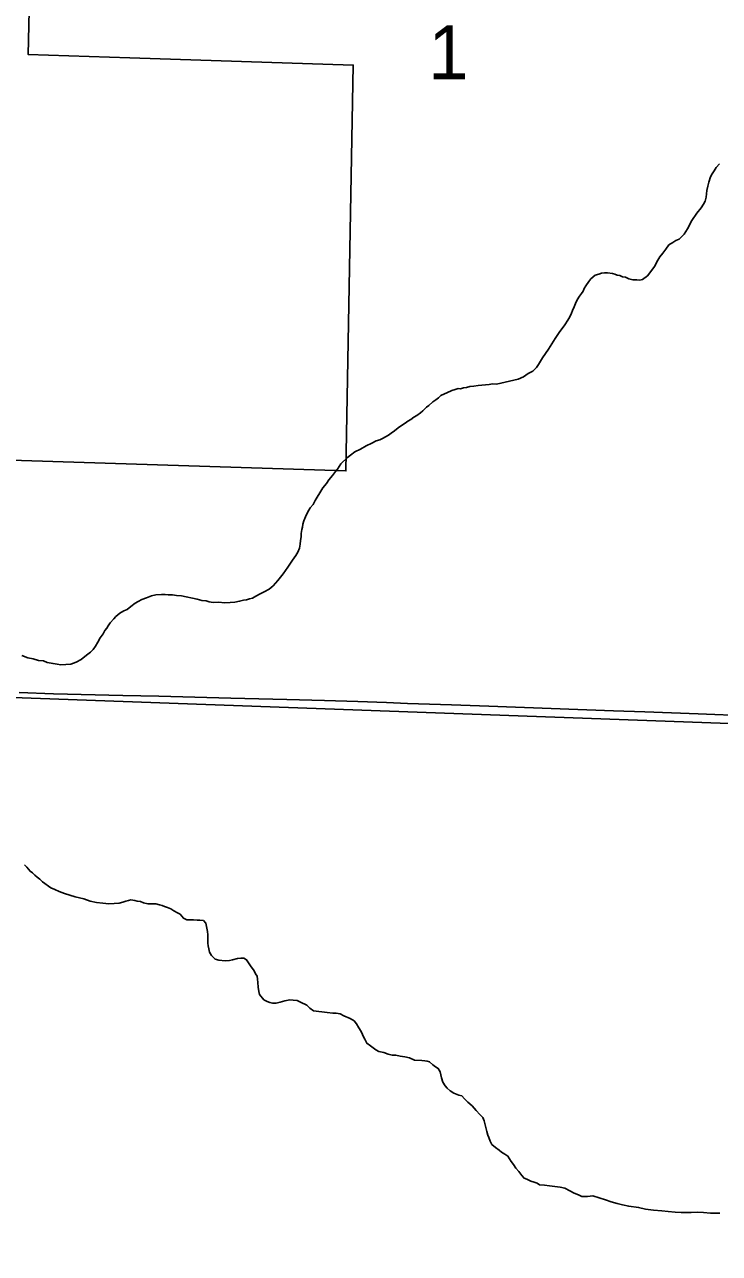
# Model space of a CAD drawing. Extents: x 0 to 34, y 0 to 22.
# Drawn here: x 6.622 to 7.163, y 14.904 to 15.859 of the extents above; entities that cross this region are included whole.
import ezdxf

# ---------------------------------------------------------------- set-up
doc = ezdxf.new("R2010")
doc.units = 0
for name, color, linetype in [('Default', 7, 'Continuous'), ('GM_X_County_Road', 7, 'Continuous'), ('GM_X_Minor_River', 7, 'Continuous'), ('GM_X_Section', 7, 'Continuous'), ('GM_X_Section_Text', 7, 'Continuous')]:
    doc.layers.add(name, color=color, linetype=linetype)

msp = doc.modelspace()

# ---------------------------------------------------------------- linework, layer by layer
at = {"layer": 'Default'}
msp.add_lwpolyline([(6.38702, 16.38807), (6.37183, 15.73038), (6.45349, 15.7281), (6.45237, 15.64429), (6.36989, 15.64692), (6.36733, 15.53569), (6.52294, 15.53156), (6.52172, 15.40421), (6.53761, 15.40378), (6.53837, 15.52309), (6.87235, 15.51249), (6.87794, 15.82798), (6.70429, 15.83364), (6.62511, 15.83621), (6.63591, 16.30343)], dxfattribs=at)
at = {"layer": 'GM_X_County_Road'}
msp.add_lwpolyline([(6.61813, 15.34005), (6.64484, 15.33924), (6.69891, 15.33794), (6.72688, 15.33731), (6.7828, 15.33586), (6.82631, 15.3347), (6.85552, 15.33398), (6.8816, 15.33321), (6.90396, 15.3323), (6.92021, 15.33172), (6.95428, 15.3305), (6.98348, 15.32953), (7.08039, 15.32594), (7.10461, 15.32503), (7.14624, 15.32359), (7.18537, 15.32196)], dxfattribs=at)
at = {"layer": 'GM_X_Minor_River'}
for points in [[(7.02362, 15.59783), (7.0252, 15.60046), (7.02755, 15.60384), (7.02991, 15.60721), (7.03228, 15.61134), (7.03503, 15.61547), (7.03818, 15.61997), (7.0425, 15.62597), (7.04486, 15.62972), (7.04644, 15.63235), (7.04764, 15.63499), (7.04845, 15.63726), (7.04965, 15.63989), (7.05085, 15.64253), (7.05205, 15.64555), (7.05401, 15.64817), (7.05558, 15.65042), (7.05677, 15.6523), (7.05757, 15.65419), (7.05876, 15.65644), (7.06112, 15.65982), (7.06268, 15.66169), (7.06617, 15.66466), (7.06885, 15.66536), (7.07115, 15.66607), (7.07344, 15.6664), (7.07573, 15.66634), (7.07952, 15.66588), (7.08142, 15.66546), (7.08331, 15.66466), (7.0852, 15.66423), (7.08747, 15.66342), (7.08974, 15.66299), (7.09238, 15.66179), (7.09541, 15.66096), (7.09846, 15.66089), (7.10074, 15.66084), (7.10303, 15.66117), (7.1069, 15.66413), (7.11239, 15.67162), (7.11399, 15.67502), (7.11635, 15.67877), (7.11871, 15.68176), (7.12105, 15.68476), (7.12341, 15.68813), (7.1265, 15.68996), (7.12881, 15.69144), (7.1315, 15.69252), (7.1354, 15.69662), (7.13777, 15.70076), (7.14133, 15.70715), (7.14526, 15.71277), (7.14839, 15.71689), (7.15036, 15.71989), (7.15156, 15.72215), (7.15238, 15.72518), (7.15288, 15.7305), (7.15371, 15.7339), (7.15453, 15.73693), (7.15577, 15.74109), (7.15696, 15.74335), (7.15853, 15.7456), (7.16011, 15.74823), (7.16284, 15.75121)], [(6.7444, 15.4152), (6.75653, 15.41264), (6.76032, 15.4118), (6.76373, 15.41134), (6.766, 15.41053), (6.76904, 15.41008), (6.77323, 15.41037), (6.77818, 15.40988), (6.78237, 15.41017), (6.7858, 15.41047), (6.78963, 15.41115), (6.79269, 15.41184), (6.79498, 15.41217), (6.79728, 15.41288), (6.79958, 15.41359), (6.80228, 15.41506), (6.80574, 15.41688), (6.80882, 15.41834), (6.81267, 15.42054), (6.81578, 15.42313), (6.81929, 15.42724), (6.82359, 15.43248), (6.82713, 15.43773), (6.83067, 15.44298), (6.83342, 15.44673), (6.835, 15.44935), (6.8362, 15.45237), (6.83665, 15.45541), (6.83709, 15.45845), (6.83753, 15.4611), (6.83759, 15.46376), (6.83803, 15.4668), (6.83845, 15.46869), (6.83888, 15.47097), (6.8397, 15.47361), (6.84091, 15.47663), (6.8425, 15.48002), (6.84449, 15.48379), (6.84683, 15.4864), (6.84842, 15.48941), (6.85, 15.49204), (6.85197, 15.49542), (6.85434, 15.49918), (6.85707, 15.50255), (6.85904, 15.50555), (6.86178, 15.50891), (6.86413, 15.51191), (6.86569, 15.51377), (6.86845, 15.5179), (6.8735, 15.52274), (6.87582, 15.52459), (6.87931, 15.52718), (6.88354, 15.52937), (6.88817, 15.53193), (6.8924, 15.53412), (6.89587, 15.53595), (6.89855, 15.53665), (6.90086, 15.53774), (6.90317, 15.53883), (6.90548, 15.5403), (6.90742, 15.54178), (6.91012, 15.54363), (6.91283, 15.54585), (6.91554, 15.54769), (6.91825, 15.54954), (6.92056, 15.55101), (6.92288, 15.55248), (6.9252, 15.55433), (6.92751, 15.55542), (6.93022, 15.55765), (6.93216, 15.55913), (6.93489, 15.56211), (6.93682, 15.56321), (6.93993, 15.56619), (6.94224, 15.56766), (6.94418, 15.56914), (6.94612, 15.571), (6.94882, 15.57246), (6.95074, 15.57318), (6.95458, 15.575), (6.95726, 15.5757), (6.95956, 15.57641), (6.96147, 15.57637), (6.96377, 15.57708), (6.96606, 15.57741), (6.96874, 15.57811), (6.97179, 15.57842), (6.97523, 15.57873), (6.9779, 15.57905), (6.98095, 15.57936), (6.98363, 15.57969), (6.9863, 15.58001), (6.98934, 15.57994), (6.99278, 15.58062), (7.00618, 15.58375), (7.01041, 15.58556), (7.01389, 15.58815), (7.01774, 15.58997), (7.02046, 15.59295), (7.02204, 15.5952), (7.02362, 15.59783)], [(6.62041, 15.36884), (6.62494, 15.36721), (6.62911, 15.36636), (6.63328, 15.36513), (6.63707, 15.36466), (6.6401, 15.36345), (6.64464, 15.36259), (6.64768, 15.36214), (6.65072, 15.36169), (6.65453, 15.36199), (6.65835, 15.36228), (6.66257, 15.36371), (6.66642, 15.36591), (6.67068, 15.36924), (6.67378, 15.37146), (6.67573, 15.3737), (6.67769, 15.37632), (6.67928, 15.37933), (6.68125, 15.38272), (6.6836, 15.38571), (6.6848, 15.38835), (6.68636, 15.39021), (6.68754, 15.39209), (6.68911, 15.39434), (6.69185, 15.39733), (6.69341, 15.3992), (6.69651, 15.40179), (6.6996, 15.40363), (6.70228, 15.40471), (6.705, 15.40693), (6.70848, 15.40952), (6.7108, 15.41099), (6.71349, 15.41246), (6.71733, 15.41389), (6.72117, 15.41533), (6.72461, 15.41602), (6.72881, 15.4163), (6.73185, 15.41624), (6.73414, 15.41619), (6.73756, 15.41611), (6.7406, 15.41566), (6.7444, 15.4152)], [(6.62227, 15.20623), (6.62413, 15.20429), (6.62673, 15.20119), (6.62861, 15.2), (6.63047, 15.19806), (6.63234, 15.19649), (6.63421, 15.19493), (6.63646, 15.19298), (6.64283, 15.18827), (6.64585, 15.18706), (6.64924, 15.18546), (6.6534, 15.18384), (6.65756, 15.18261), (6.66172, 15.18138), (6.66854, 15.1797), (6.67346, 15.17807), (6.67838, 15.17682), (6.68332, 15.17633), (6.68788, 15.17585), (6.69207, 15.17613), (6.69589, 15.17643)], [(6.69589, 15.17643), (6.69895, 15.17712), (6.70125, 15.17783), (6.70317, 15.17855), (6.70508, 15.17889), (6.70812, 15.17844), (6.71001, 15.17802), (6.71267, 15.17758), (6.71494, 15.17677), (6.71835, 15.17593), (6.72025, 15.17589), (6.72215, 15.17585), (6.72443, 15.1758), (6.72746, 15.17497), (6.72936, 15.17454), (6.73125, 15.17374), (6.73351, 15.17293), (6.73616, 15.17211), (6.73841, 15.17054), (6.74143, 15.16895), (6.7433, 15.16776), (6.7459, 15.16466), (6.74854, 15.16346), (6.75387, 15.16334), (6.75653, 15.16328), (6.75882, 15.16323), (6.76148, 15.16279), (6.76334, 15.16085), (6.76472, 15.15434), (6.76505, 15.15167), (6.765, 15.14939), (6.76496, 15.14749), (6.76491, 15.1452), (6.76525, 15.14329), (6.76558, 15.141), (6.76628, 15.13832), (6.76775, 15.13562), (6.77074, 15.13289), (6.77339, 15.13207), (6.77832, 15.13158), (6.78176, 15.13189), (6.78405, 15.13222), (6.78788, 15.13327), (6.79056, 15.13359), (6.79284, 15.13354), (6.7951, 15.13235), (6.79804, 15.12772), (6.80101, 15.12384), (6.8021, 15.12154), (6.8032, 15.11961), (6.80353, 15.11732), (6.80386, 15.11464), (6.80417, 15.11121), (6.80447, 15.10778), (6.80519, 15.10548), (6.80852, 15.10122), (6.81116, 15.10002), (6.81305, 15.09921), (6.81532, 15.09878), (6.81799, 15.09872), (6.82105, 15.09942), (6.82488, 15.10047), (6.82871, 15.10115), (6.83137, 15.10109), (6.8344, 15.10064), (6.83704, 15.09944), (6.84194, 15.09705), (6.84418, 15.09472), (6.84718, 15.09275), (6.85782, 15.09137), (6.862, 15.09089), (6.86466, 15.09083), (6.8677, 15.09039), (6.87071, 15.0888), (6.87562, 15.08679), (6.87862, 15.08481), (6.88048, 15.08249), (6.88231, 15.0794), (6.88416, 15.0767), (6.88525, 15.07439), (6.88597, 15.07247), (6.88707, 15.07054), (6.88853, 15.06746), (6.89154, 15.06549), (6.89341, 15.06393), (6.89566, 15.06236), (6.89792, 15.06116), (6.90171, 15.06032), (6.90511, 15.0591), (6.90814, 15.05827), (6.91118, 15.0582), (6.91459, 15.05737), (6.91801, 15.05691), (6.9218, 15.05606), (6.92557, 15.05446), (6.93127, 15.05395), (6.93356, 15.0539), (6.93545, 15.05348), (6.93735, 15.05306), (6.93996, 15.05071), (6.94183, 15.04915)], [(6.94183, 15.04915), (6.94409, 15.04796), (6.94556, 15.04526), (6.9466, 15.04067), (6.94767, 15.03722), (6.94952, 15.03451), (6.951, 15.03258), (6.95324, 15.03062), (6.95625, 15.02865), (6.96002, 15.02705), (6.9623, 15.02662), (6.96453, 15.02428), (6.96714, 15.02156), (6.97051, 15.01882), (6.97348, 15.01533), (6.97646, 15.01221), (6.9787, 15.00988), (6.97978, 15.00719), (6.98083, 15.00298), (6.98189, 14.99877), (6.98259, 14.99609), (6.98331, 14.99417), (6.98439, 14.99148), (6.98586, 14.98878), (6.98848, 14.98644), (6.99148, 14.98447), (6.99335, 14.98291), (6.99598, 14.98133), (6.99823, 14.97975), (7.00081, 14.97551), (7.00266, 14.97318), (7.00451, 14.97048), (7.00674, 14.96776), (7.00896, 14.96467), (7.01082, 14.96272), (7.01309, 14.96191), (7.0161, 14.96032), (7.01875, 14.9595), (7.02101, 14.95869), (7.02289, 14.9575), (7.02669, 14.95704), (7.03049, 14.95657), (7.03467, 14.9561), (7.03885, 14.95563), (7.04264, 14.95478), (7.0464, 14.9528), (7.04979, 14.95082), (7.05319, 14.9496), (7.05583, 14.9484), (7.05773, 14.94836), (7.06001, 14.94831), (7.06422, 14.94897), (7.07405, 14.94571), (7.07858, 14.94409), (7.08313, 14.94284), (7.0873, 14.94199), (7.09222, 14.94074), (7.09982, 14.93981), (7.10512, 14.93855), (7.11158, 14.93764), (7.11804, 14.93712), (7.12298, 14.93663), (7.1283, 14.93613), (7.13287, 14.93603), (7.13667, 14.93594), (7.14086, 14.93585), (7.14543, 14.93613), (7.15038, 14.93602), (7.1557, 14.93552), (7.16293, 14.93536)]]:
    msp.add_lwpolyline(points, dxfattribs=at)
at = {"layer": 'GM_X_Section'}
for points in [[(6.38559, 16.38675), (7.38494, 16.36973), (7.37037, 15.30881), (6.36308, 15.34539)], [(6.36308, 15.34539), (7.37037, 15.30881), (7.35443, 14.30981), (6.34437, 14.33999)]]:
    msp.add_lwpolyline(points, close=True, dxfattribs=at)

# ---------------------------------------------------------------- texts
at = {"layer": 'GM_X_Section_Text'}
msp.add_text('1', height=0.04186, rotation=0.00001, dxfattribs=at).set_placement((6.93639, 15.81698))

doc.saveas('drawing.dxf')
